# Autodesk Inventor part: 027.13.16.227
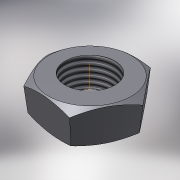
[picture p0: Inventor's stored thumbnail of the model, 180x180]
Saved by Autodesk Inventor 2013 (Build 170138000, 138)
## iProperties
Shininess: 64.0
Length Units: 11269
Angle Units: 11279
Time Units: 11290
Mass Units: 11283
Length Display Precision: 3
Angle Display Precision: 2
Created: 2002-02
Part Number: 027.13.16.227
Material: Steel, Mild
Document SubType Name: Modeling
Designer: SOleg
Density: 7.86 g/cm^3
Density: 0.0
Volumn: 0.0
Area: 0.0
PropertySet Name: Model Information
Control State: 0
Master: False
Checked Out: True
Author: SOleg
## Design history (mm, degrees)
sketch "Sketch1"
  geometry: L1 (9.815, 17)-(19.63, 0); L2 (19.63, 0)-(9.815, -17); L3 (9.815, -17)-(-9.815, -17); L4 (-9.815, -17)-(-19.63, 0); L5 (-19.63, 0)-(-9.815, 17); L6 (-9.815, 17)-(9.815, 17); C1 r 10 at (0, 0); 3 further points
  constraints: 12 end point, 2 coincident, 1 centre point, 1 midpoint, 1 vertical alignment, 13 other
  dimensions: "d1" = 20 diameter of C1
extrude "Extrusion1" new body sketch "Sketch1" distance "d2" = 13.5; taper "d3" = 0 deg
node "РабОсь1"
sketch "Sketch2"
  geometry: L1 (-16.5, 13.5)-(-19.942, 13.5); L2 (0, 45)-(0, -1.383); L3 (-16.5, 13.5)-(-19.942, 11.513); L4 (-19.942, 11.513)-(-19.942, 13.5); L5 (17, 0)-(17, 13.5) reference; L6 (17, 6.75)-(-24.004, 6.75); L7 (-16.5, 0)-(-19.942, 0); L8 (-16.5, 0)-(-19.942, 1.987); L9 (-19.942, 1.987)-(-19.942, 0); L10 (0, -10.66)-(0, 54.277) reference; L11 (10, 0)-(-10, 0) reference; L12 (17, 0)-(0, 0) reference; L13 (0, 0)-(-17, 0) reference; L14 (-17, 0)-(0, 0) reference; L15 (0, 0)-(17, 0) reference; L16 (-10, 13.5)-(10, 13.5) reference; L17 (17, 13.5)-(0, 13.5) reference; L18 (0, 13.5)-(17, 13.5) reference; L19 (-17, 13.5)-(0, 13.5) reference; L20 (0, 13.5)-(-17, 13.5) reference
  constraints: 16 end point, 3 collinear, 3 symmetric about line, 2 perpendicular, 1 midpoint, 3 other
  dimensions: "d5" = 30 deg angle of L1 L3; "d9" = 33 diameter of L7.start L2
revolve "Revolution1" sketch "Sketch2" stored, may be unused: angle "d6" = 90 deg
thread "Thread1" dims "d7" = 10, "d8" = 0
body "Solid1"
node "Спроецированная петля1"
node "Спроецированная петля2"
other parameters: "d0" = 34
